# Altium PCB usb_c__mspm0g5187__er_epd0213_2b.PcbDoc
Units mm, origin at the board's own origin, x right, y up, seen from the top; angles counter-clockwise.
Board outline 82 x 52 mm, 2 copper layers (Top, Bottom), stack 0 mm thick; 41 components, 34 nets, 208 pads, 91 vias.
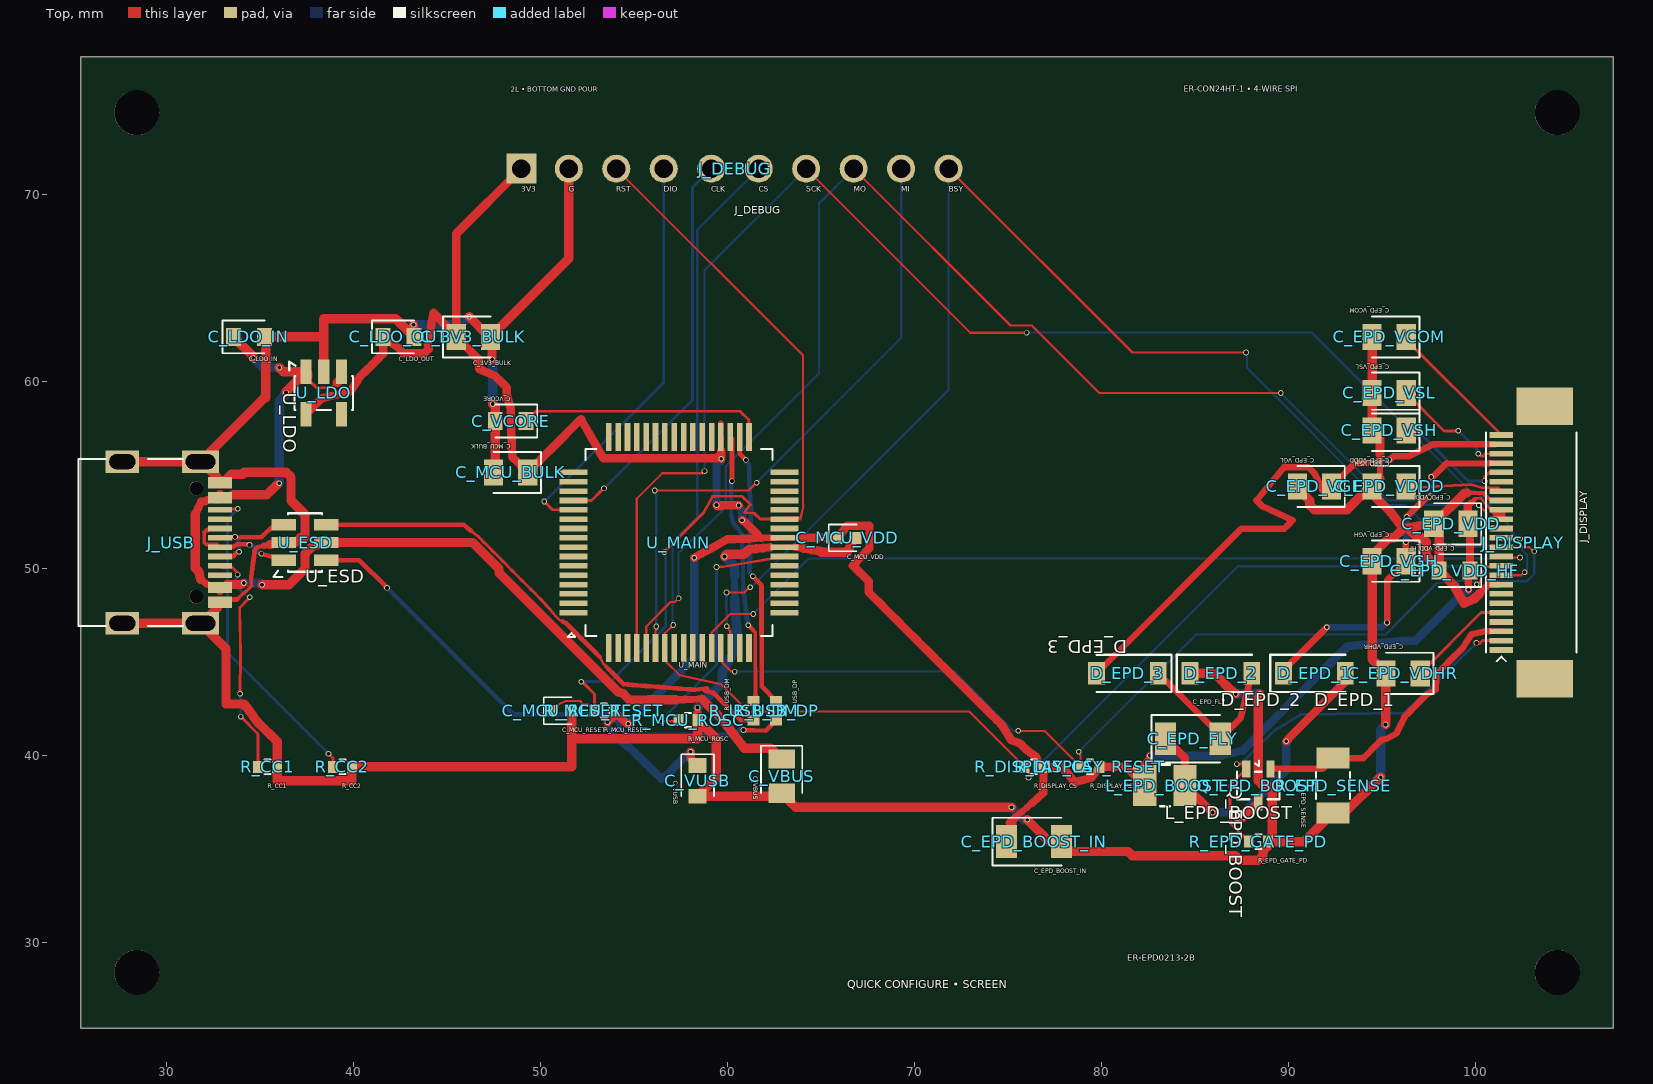
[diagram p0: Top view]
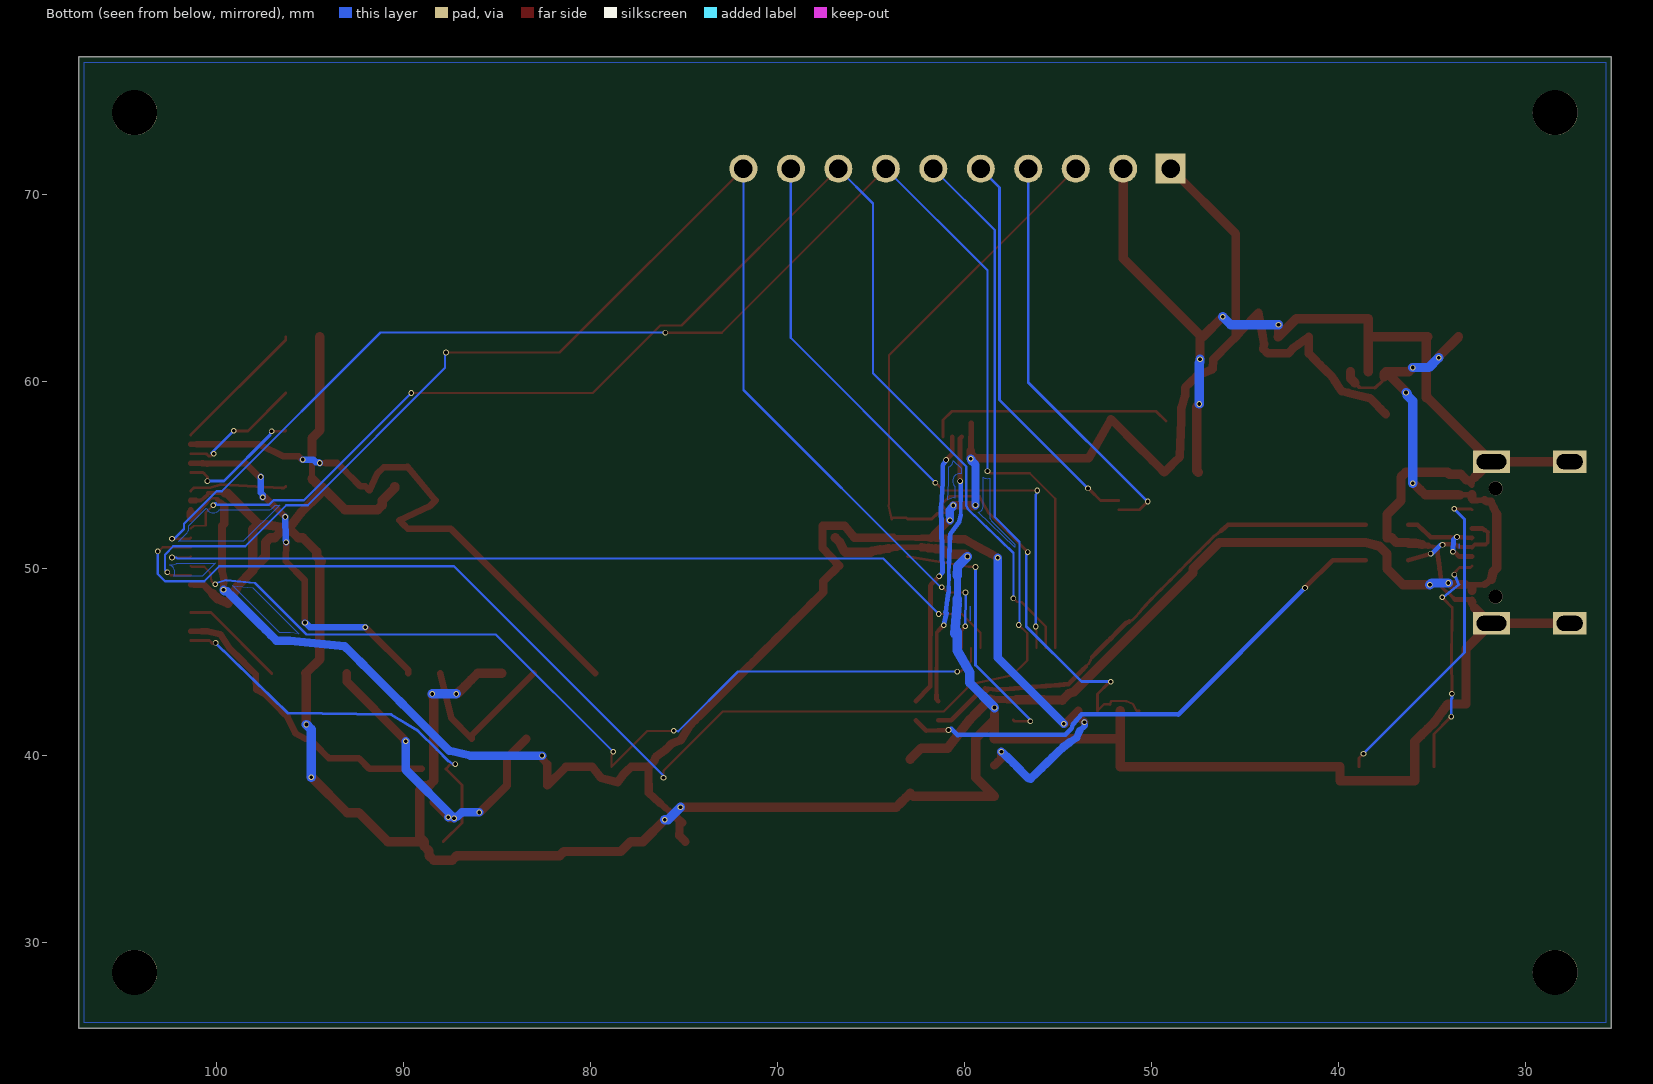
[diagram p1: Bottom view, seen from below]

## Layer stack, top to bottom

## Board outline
25.4,77.4 107.4,77.4 107.4,25.4 25.4,25.4

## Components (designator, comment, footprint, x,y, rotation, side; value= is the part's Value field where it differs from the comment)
C_3V3_BULK "" TSCIRCUIT-2.8500x1.4000mm 46.4,62.4 r0 top
C_EPD_BOOST_IN "" TSCIRCUIT-4.0500x1.7500mm 76.4,35.4 r0 top
C_EPD_FLY "" TSCIRCUIT-4.0500x1.7500mm 84.9,40.9 r0 top
C_EPD_VCOM "" TSCIRCUIT-2.8500x1.4000mm 95.4,62.4 r180 top
C_EPD_VDD "" TSCIRCUIT-2.8500x1.4000mm 98.7,52.4 r180 top
C_EPD_VDD_HF "" TSCIRCUIT-2.4500x0.9500mm 98.9,49.9 r180 top
C_EPD_VDDD "" TSCIRCUIT-2.8500x1.4000mm 95.4,54.4 r180 top
C_EPD_VDHR "" TSCIRCUIT-2.8500x1.4000mm 96.15,44.4 r180 top
C_EPD_VGH "" TSCIRCUIT-2.8500x1.4000mm 95.4,50.4 r180 top
C_EPD_VGL "" TSCIRCUIT-2.8500x1.4000mm 91.4,54.4 r180 top
C_EPD_VSH "" TSCIRCUIT-2.8500x1.4000mm 95.4,57.4 r180 top
C_EPD_VSL "" TSCIRCUIT-2.8500x1.4000mm 95.4,59.4 r180 top
C_LDO_IN "" TSCIRCUIT-2.4500x0.9500mm 34.4,62.4 r0 top
C_LDO_OUT "" TSCIRCUIT-2.4500x0.9500mm 42.4,62.4 r0 top
C_MCU_BULK "" TSCIRCUIT-2.8500x1.4000mm 48.4,55.15 r180 top
C_MCU_RESET "" TSCIRCUIT-1.5600x0.6400mm 51.15,42.4 r0 top
C_MCU_VDD "" TSCIRCUIT-1.5600x0.6400mm 66.4,51.65 r0 top
C_VBUS "" TSCIRCUIT-1.4000x2.8500mm 62.9,38.9 r270 top
C_VCORE "" TSCIRCUIT-2.4500x0.9500mm 48.4,57.9 r180 top
C_VUSB "" TSCIRCUIT-0.9500x2.4500mm 58.4,38.65 r270 top
D_EPD_1 "" TSCIRCUIT-4.2000x1.2000mm 91.4,44.4 r0 top
D_EPD_2 "" TSCIRCUIT-4.2000x1.2000mm 86.4,44.4 r0 top
D_EPD_3 "" TSCIRCUIT-4.2000x1.2000mm 81.4,44.4 r180 top
J_DEBUG "" TSCIRCUIT-24.3600x1.5000mm 60.4,71.4 r0 top
J_DISPLAY "" TSCIRCUIT-4.4500x16.5800mm 103,51.4 r90 top
J_USB "" TSCIRCUIT-6.7732x9.8502mm 30.113,51.4 r90 top
L_EPD_BOOST "" TSCIRCUIT-3.4000x2.2000mm 83.4,38.4 r0 top
Q_EPD_BOOST "" TSCIRCUIT-1.7500x2.7000mm 88.4,38.4 r270 top
R_CC1 "" TSCIRCUIT-1.5600x0.6400mm 35.4,39.4 r0 top
R_CC2 "" TSCIRCUIT-1.5600x0.6400mm 39.4,39.4 r0 top
R_DISPLAY_CS "" TSCIRCUIT-1.5600x0.6400mm 76.4,39.4 r0 top
R_DISPLAY_RESET "" TSCIRCUIT-1.5600x0.6400mm 79.4,39.4 r0 top
R_EPD_GATE_PD "" TSCIRCUIT-1.5600x0.6400mm 88.4,35.4 r0 top
R_EPD_SENSE "" TSCIRCUIT-1.7500x4.0500mm 92.4,38.4 r270 top
R_MCU_RESET "" TSCIRCUIT-1.5600x0.6400mm 53.4,42.4 r0 top
R_MCU_ROSC "" TSCIRCUIT-1.5600x0.6400mm 57.9,41.9 r0 top
R_USB_DM "" TSCIRCUIT-0.6400x1.5600mm 61.4,42.4 r90 top
R_USB_DP "" TSCIRCUIT-0.6400x1.5600mm 62.6,42.4 r90 top
U_ESD "" TSCIRCUIT-3.6000x2.5000mm 37.4,51.4 r0 top
U_LDO "" TSCIRCUIT-2.5000x3.6000mm 38.4,59.4 r270 top
U_MAIN "" TSCIRCUIT-12.8000x12.8000mm 57.4,51.4 r0 top

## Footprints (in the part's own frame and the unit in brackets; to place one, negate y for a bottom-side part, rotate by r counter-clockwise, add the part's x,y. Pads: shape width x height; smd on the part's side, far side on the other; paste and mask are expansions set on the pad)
TSCIRCUIT-0.6400x1.5600mm [mm]
  rect 0.54x0.64 smd: 1(-0.51,0) 2(0.51,0)
  silkscreen extent -0.15,-0.38 0.15,0.38
TSCIRCUIT-0.9500x2.4500mm [mm]
  rect 0.8x0.95 smd: 1(-0.825,0) 2(0.825,0)
  silkscreen extent -1.43,-0.87 0.82,0.87
TSCIRCUIT-1.4000x2.8500mm [mm]
  rect 1.025x1.4 smd: 1(-0.913,0) 2(0.913,0)
  silkscreen extent -1.62,-1.1 0.91,1.1
TSCIRCUIT-1.5600x0.6400mm [mm]
  rect 0.54x0.64 smd: 1(-0.51,0) 2(0.51,0)
  silkscreen extent -0.98,-0.72 0.51,0.72
TSCIRCUIT-1.7500x2.7000mm [mm]
  rect 0.925x0.45 smd: 1(-0.888,-0.65) 2(-0.888,0.65) 3(0.887,0)
  silkscreen extent -1.32,-1.14 0.73,1.13
TSCIRCUIT-1.7500x4.0500mm [mm]
  rect 1.125x1.75 smd: 1(-1.463,0) 2(1.462,0)
  silkscreen extent -0.73,-0.91 0.73,0.91
TSCIRCUIT-2.4500x0.9500mm [mm]
  rect 0.8x0.95 smd: 1(-0.825,0) 2(0.825,0)
  silkscreen extent -1.42,-0.87 0.82,0.87
TSCIRCUIT-2.5000x3.6000mm [mm]
  rect 1.325x0.6 smd: 1(-1.137,-0.95) 2(-1.137,0) 3(-1.137,0.95) 4(1.138,0.95) 5(1.138,-0.95)
  silkscreen extent -1.69,-1.84 0.91,1.56
TSCIRCUIT-2.8500x1.4000mm [mm]
  rect 1.025x1.4 smd: 1(-0.913,0) 2(0.913,0)
  silkscreen extent -1.63,-1.1 0.91,1.1
TSCIRCUIT-3.4000x2.2000mm [mm]
  rect 1.25x2.2 smd: 1(-1.075,0) 2(1.075,0)
  silkscreen extent -0.26,-1.11 0.26,1.11
TSCIRCUIT-3.6000x2.5000mm [mm]
  rect 1.325x0.6 smd: 1(-1.137,-0.95) 2(-1.137,0) 3(-1.137,0.95) 4(1.138,0.95) 5(1.138,0) 6(1.138,-0.95)
  silkscreen extent -1.69,-1.84 0.91,1.56
TSCIRCUIT-4.0500x1.7500mm [mm]
  rect 1.125x1.75 smd: 1(-1.462,0) 2(1.463,0)
  silkscreen extent -2.22,-1.28 1.46,1.27
TSCIRCUIT-4.2000x1.2000mm [mm]
  rect 0.9x1.2 smd: 1(-1.65,0) 2(1.65,0)
  silkscreen extent -2.36,-1 1.65,1
TSCIRCUIT-4.4500x16.5800mm [mm]
  rect 0.3x1.25 smd: 1(-5.75,1.6) 2(-5.25,1.6) 3(-4.75,1.6) 4(-4.25,1.6) 5(-3.75,1.6) 6(-3.25,1.6) 7(-2.75,1.6) 8(-2.25,1.6) 9(-1.75,1.6) 10(-1.25,1.6) 11(-0.75,1.6) 12(-0.25,1.6) 13(0.25,1.6) 14(0.75,1.6) 15(1.25,1.6) 16(1.75,1.6) 17(2.25,1.6) 18(2.75,1.6) 19(3.25,1.6) 20(3.75,1.6) 21(4.25,1.6) 22(4.75,1.6) 23(5.25,1.6) 24(5.75,1.6)
  rect 2x3 smd: 25(7.29,-0.725) 26(-7.29,-0.725)
  silkscreen extent -6.35,-2.43 5.9,2.42
TSCIRCUIT-6.7732x9.8502mm [mm]
  rect 0.3x1.3 smd: 1(-3.35,-2.737) 2(-3.05,-2.737) 3(-2.55,-2.737) 4(-2.25,-2.737) 5(-1.75,-2.737) 6(-1.25,-2.737) 7(-0.75,-2.737) 8(-0.25,-2.737) 9(0.25,-2.737) 10(0.75,-2.737) 11(1.25,-2.737) 12(1.75,-2.737) 13(2.55,-2.737) 14(2.25,-2.737) 15(3.35,-2.737) 16(3.05,-2.737)
  rect 1.2x2 hole 0.8 slot 1.6 at 90 deg: 17(-4.325,-1.693) 18(4.325,-1.693)
  rect 1.2x1.8 hole 0.8 slot 1.4 at 90 deg: 19(4.325,2.487) 20(-4.325,2.487)
  round 0.75 hole 0.75 unplated: NPTH-1(-2.9,-1.468) NPTH-2(2.9,-1.468)
  silkscreen extent -4.47,-0.75 4.47,4.83
TSCIRCUIT-12.8000x12.8000mm [mm]
  rect 1.5x0.3 smd: 1(-5.65,-3.75) 2(-5.65,-3.25) 3(-5.65,-2.75) 4(-5.65,-2.25) 5(-5.65,-1.75) 6(-5.65,-1.25) 7(-5.65,-0.75) 8(-5.65,-0.25) 9(-5.65,0.25) 10(-5.65,0.75) 11(-5.65,1.25) 12(-5.65,1.75) 13(-5.65,2.25) 14(-5.65,2.75) 15(-5.65,3.25) 16(-5.65,3.75) 33(5.65,3.75) 34(5.65,3.25) 35(5.65,2.75) 36(5.65,2.25) 37(5.65,1.75) 38(5.65,1.25) 39(5.65,0.75) 40(5.65,0.25) 41(5.65,-0.25) 42(5.65,-0.75) 43(5.65,-1.25) 44(5.65,-1.75) 45(5.65,-2.25) 46(5.65,-2.75) 47(5.65,-3.25) 48(5.65,-3.75)
  rect 0.3x1.5 smd: 17(-3.75,5.65) 18(-3.25,5.65) 19(-2.75,5.65) 20(-2.25,5.65) 21(-1.75,5.65) 22(-1.25,5.65) 23(-0.75,5.65) 24(-0.25,5.65) 25(0.25,5.65) 26(0.75,5.65) 27(1.25,5.65) 28(1.75,5.65) 29(2.25,5.65) 30(2.75,5.65) 31(3.25,5.65) 32(3.75,5.65) 49(3.75,-5.65) 50(3.25,-5.65) 51(2.75,-5.65) 52(2.25,-5.65) 53(1.75,-5.65) 54(1.25,-5.65) 55(0.75,-5.65) 56(0.25,-5.65) 57(-0.25,-5.65) 58(-0.75,-5.65) 59(-1.25,-5.65) 60(-1.75,-5.65) 61(-2.25,-5.65) 62(-2.75,-5.65) 63(-3.25,-5.65) 64(-3.75,-5.65)
  silkscreen extent -5.95,-5.05 5,5
TSCIRCUIT-24.3600x1.5000mm [mm]
  rect 1.6x1.6 hole 1: 1(-11.43,0)
  round 1.5 hole 1: 2(-8.89,0) 3(-6.35,0) 4(-3.81,0) 5(-1.27,0) 6(1.27,0) 7(3.81,0) 8(6.35,0) 9(8.89,0) 10(11.43,0)

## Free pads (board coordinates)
  round 2.4 hole 2.4 unplated: NPTH-3(28.4,28.4) NPTH-4(104.4,28.4) NPTH-5(28.4,74.4) NPTH-6(104.4,74.4)

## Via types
v1: diameter 0.3, hole 0.2, Top to Bottom, 91 vias

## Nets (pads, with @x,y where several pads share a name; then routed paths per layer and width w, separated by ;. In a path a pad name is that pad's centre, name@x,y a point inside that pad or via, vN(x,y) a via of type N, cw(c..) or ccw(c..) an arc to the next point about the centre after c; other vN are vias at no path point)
".J_DEBUG > .pin4 to .U_MAIN > .pin12": J_DEBUG.4 U_MAIN.12 | length 22.2
  Top w0.15: v1(50.2,53.593) 50.643,53.15 U_MAIN.12
  Bottom w0.15: v1(50.2,53.593) 50.215,53.593 56.59,59.968 J_DEBUG.4
".J_DEBUG > .pin5 to .U_MAIN > .pin13": J_DEBUG.5 U_MAIN.13 | length 21.4
  Top w0.15: U_MAIN.13 52.732,53.65 53.275,54.193 53.293,54.193 v1(53.395,54.295)
  Bottom w0.15: v1(53.395,54.295) 58.128,59.028 58.128,70.316 58.128,70.398 J_DEBUG.5
".J_DISPLAY > .pin5 to .C_EPD_VDHR > .pin1": C_EPD_VDHR.1 J_DISPLAY.5 | length 5.7
  Top w0.15: C_EPD_VDHR.1 100.313,47.65 J_DISPLAY.5
".J_DISPLAY > .pin18 to .C_EPD_VDDD > .pin1": C_EPD_VDDD.1 J_DISPLAY.18 | length 5.2
  Top w0.15: C_EPD_VDDD.1 96.403,54.31 96.526,54.31 99.77,54.5 100.358,54.332 101.24,54.31 J_DISPLAY.18
".J_DISPLAY > .pin20 to .C_EPD_VSH > .pin1": C_EPD_VSH.1 J_DISPLAY.20 | length 6.6
  Top w0.15: C_EPD_VSH.1 96.362,57.351 v1(97.07,57.351) ; v1(100.503,54.686) 100.503,54.911 100.677,55.085 100.742,55.15 J_DISPLAY.20
  Bottom w0.15: v1(97.07,57.351) 97.144,57.277 97.144,57.166 99.624,54.686 v1(100.503,54.686)
".J_DISPLAY > .pin22 to .C_EPD_VSL > .pin1": C_EPD_VSL.1 J_DISPLAY.22 | length 6.8
  Top w0.15: C_EPD_VSL.1 98.341,57.372 v1(99.099,57.372) ; v1(100.159,56.142) 100.305,56.031 100.449,56.031 100.568,56.15 J_DISPLAY.22
  Bottom w0.15: v1(99.099,57.372) 99.157,57.314 100.289,56.182 v1(100.159,56.142)
".J_DISPLAY > .pin24 to .C_EPD_VCOM > .pin1": C_EPD_VCOM.1 J_DISPLAY.24 | length 7.4
  Top w0.15: C_EPD_VCOM.1 96.312,62.238 J_DISPLAY.24
".U_MAIN > .pin42 to .R_MCU_ROSC > .pin1": R_MCU_ROSC.1 U_MAIN.42 | length 14.1
  Top w0.15: v1(56.473,41.835) 57.325,41.835 R_MCU_ROSC.1 ; v1(59.411,50.089) 59.429,50.107 59.777,50.106 U_MAIN.42
  Bottom w0.15: v1(56.473,41.835) 56.447,41.861 56.447,41.875 59.411,44.838 v1(59.411,50.089)
DISPLAY_BUSY_N: J_DEBUG.10 J_DISPLAY.9 U_MAIN.51 | length 73.5
  Top w0.12: v1(59.945,48.725) 60.896,48.725 61.106,48.935 61.158,48.935 v1(61.223,49) ; v1(59.964,46.92) 60.093,46.817 60.093,46.726 60.15,46.67 U_MAIN.51 ; J_DEBUG.10 81.666,61.564 v1(87.742,61.564) ; J_DISPLAY.9 102.472,49.65 102.598,49.776 102.612,49.776 v1(102.645,49.809)
  Bottom w0.12: v1(59.945,48.725) 59.936,48.716 59.936,48.646 v1(59.964,46.92) ; v1(61.223,49) 61.267,49 71.83,59.563 J_DEBUG.10 ; v1(87.742,61.564) 87.788,61.518 87.788,61.482 87.788,60.745 95.141,53.392 96.285,53.392 98.48,51.197 102.335,51.197 102.78,50.752 102.78,49.944 v1(102.645,49.809)
DISPLAY_CS_N: J_DEBUG.6 J_DISPLAY.12 R_DISPLAY_CS.1 U_MAIN.58 | length 85.9
  Top w0.12: v1(57.094,46.987) 56.65,46.543 U_MAIN.58 56.65,45.093 57.449,44.294 59.655,43.814 61.112,42.358 72.932,42.358 R_DISPLAY_CS.1 76.106,39.184 v1(76.106,38.818) ; J_DISPLAY.12 102.897,51.15 103.076,50.971 103.117,50.971 v1(103.166,50.922)
  Bottom w0.12: v1(57.094,46.987) 57.056,47.025 57.056,47.046 57.056,51.428 58.388,52.759 58.388,68.118 J_DEBUG.6 ; v1(76.106,38.818) 76.055,38.869 87.316,50.131 99.877,50.131 100.675,49.333 102.779,49.333 103.166,49.72 v1(103.166,50.922)
DISPLAY_DC: J_DISPLAY.11 U_MAIN.53 | length 46.8
  Top w0.12: U_MAIN.53 59.15,46.572 60.16,47.582 61.321,47.582 61.347,47.608 v1(61.381,47.574) ; J_DISPLAY.11 101.45,50.6 v1(102.4,50.6)
  Bottom w0.12: v1(61.381,47.574) 64.353,50.546 95.398,50.546 102.123,50.546 102.177,50.6 v1(102.4,50.6)
DISPLAY_MISO: J_DEBUG.9 U_MAIN.59 | length 34.1
  Top w0.12: v1(56.115,54.184) 61.124,54.184 61.468,54.528 v1(61.557,54.599) ; U_MAIN.59 56.15,46.685 56.196,46.731 56.196,46.895 v1(56.186,46.905)
  Bottom w0.12: v1(56.115,54.184) 56.058,54.127 56.058,54.101 56.186,53.973 v1(56.186,46.905) ; v1(61.557,54.599) 69.29,62.35 J_DEBUG.9
DISPLAY_MOSI: J_DEBUG.8 J_DISPLAY.14 U_MAIN.60 | length 73.5
  Top w0.12: U_MAIN.60 55.65,46.912 56.95,48.212 57.186,48.212 v1(57.383,48.409) ; J_DEBUG.8 75.137,63.013 76.276,63.013 79.888,59.4 89.529,59.4 v1(89.6,59.4) ; v1(100.191,53.388) 100.591,53.008 100.591,52.312 101.228,52.289 J_DISPLAY.14
  Bottom w0.12: v1(57.383,48.409) 57.383,50.842 59.826,53.195 59.904,53.363 59.904,55.468 60.536,56.099 64.891,60.454 64.891,69.541 J_DEBUG.8 ; v1(89.6,59.4) 95.341,53.659 96.97,53.659 97.211,53.419 99.868,53.419 99.98,53.419 100.076,53.515 100.084,53.515 v1(100.191,53.388)
DISPLAY_RESET_N: J_DISPLAY.10 R_DISPLAY_RESET.1 U_MAIN.52 | length 50.1
  Top w0.12: U_MAIN.52 59.65,45.051 59.863,44.838 60.207,44.494 v1(60.392,44.494) ; v1(75.556,41.328) 76.991,41.299 R_DISPLAY_RESET.1 78.89,40.022 78.799,40.112 v1(78.799,40.203) ; v1(100.086,49.16) 100.285,49.33 100.347,49.778 100.673,50.103 101.353,50.103 J_DISPLAY.10
  Bottom w0.12: v1(60.392,44.494) 72.12,44.494 75.315,41.299 v1(75.556,41.328) ; v1(78.799,40.203) 85.074,46.478 95.197,46.478 97.957,49.238 99.513,49.386 100.03,49.238 v1(100.086,49.16)
DISPLAY_SCLK: J_DEBUG.7 J_DISPLAY.13 U_MAIN.61 | length 78.2
  Top w0.12: U_MAIN.61 55.15,53.743 56.507,55.1 58.65,55.1 58.726,55.176 v1(58.77,55.22) ; J_DEBUG.7 72.984,62.626 75.825,62.626 75.996,62.626 v1(76,62.63) ; J_DISPLAY.13 101.45,51.6 v1(102.4,51.6)
  Bottom w0.12: v1(58.77,55.22) 58.77,65.96 J_DEBUG.7 ; v1(76,62.63) 91.241,62.63 99.732,54.139 100.023,54.139 101.761,52.402 101.761,52.117 102.265,51.612 102.388,51.612 v1(102.4,51.6)
EPD_GDR: J_DISPLAY.2 Q_EPD_BOOST.1 R_EPD_GATE_PD.1 | length 22
  Top w0.15: v1(87.248,39.546) 87.491,39.546 Q_EPD_BOOST.1 86.892,38.43 86.892,36.398 R_EPD_GATE_PD.1 ; v1(100.067,46.029) 100.114,45.982 100.22,45.982 100.388,46.15 J_DISPLAY.2
  Bottom w0.15: v1(87.248,39.546) 87.252,39.55 87.381,39.55 87.617,39.717 88.226,40.318 89.234,41.325 90.667,42.196 96.208,42.284 v1(100.067,46.029)
EPD_PUMP: C_EPD_FLY.2 D_EPD_2.2 D_EPD_3.1 | length 8.9
  Top w0.35: D_EPD_3.1 86.362,41.087 C_EPD_FLY.2 87.468,42.025 D_EPD_2.2
EPD_RESE: J_DISPLAY.3 Q_EPD_BOOST.2 R_EPD_SENSE.1 | length 16
  Top w0.3: J_DISPLAY.3@100.812,46.65 101.106,46.65 J_DISPLAY.3
  Top w0.35: Q_EPD_BOOST.2 91.826,39.288 R_EPD_SENSE.1 92.721,39.862 93.042,39.861 93.364,39.861 93.685,39.86 94.006,39.86 94.251,40.105 94.496,40.35 94.741,40.595 94.985,40.84 95.275,40.9 95.801,41.191 96.21,42.064 96.454,42.309 96.699,42.554 96.944,42.799 97.189,43.044 97.434,43.289 97.9,43.525 97.923,44.063 97.922,44.348 98.159,44.585 98.396,44.822 98.633,45.059 98.87,45.296 99.107,45.533 99.344,45.77 99.825,46.5 100.518,46.65 J_DISPLAY.3@100.812,46.65
EPD_SWITCH: C_EPD_FLY.1 D_EPD_1.2 L_EPD_BOOST.2 Q_EPD_BOOST.3 | length 19.6
  Top w0.45: C_EPD_FLY.1 84.475,39.863 L_EPD_BOOST.2 84.48,38.4 85.879,37.001 85.924,37.001 v1(85.963,36.962) ; v1(87.308,36.655) v1@87.543,36.655 ; v1(87.625,36.7) v1@87.543,36.655 ; v1(89.894,40.764) 90.006,40.876 90.006,40.911 93.05,43.954 D_EPD_1.2 ; v1@87.543,36.655 Q_EPD_BOOST.3 v1@87.543,36.655
  Bottom w0.45: v1(85.963,36.962) 86.9,36.962 87.12,36.741 87.222,36.741 v1(87.625,36.7) ; v1(87.308,36.655) 87.344,36.691 89.894,39.241 v1(89.894,40.764)
EPD_VGH: C_EPD_VGH.1 D_EPD_1.1 J_DISPLAY.21 | length 19.7
  Top w0.3: 100.775,55.65 100.837,55.65 100.931,55.65 101.025,55.65 101.119,55.65 101.213,55.65 101.306,55.65 J_DISPLAY.21
  Top w0.35: D_EPD_1.1 89.75,44.56 91.935,46.745 91.938,46.745 v1(92.064,46.871) ; v1(95.285,47.116) 95.285,49.372 C_EPD_VGH.1 96.321,50.408 v1(96.294,51.409) ; v1(96.341,52.77) 96.431,52.859 96.435,52.859 97.391,53.815 v1(97.537,53.815) ; v1(97.649,54.908) 97.663,54.894 97.713,54.894 98.469,55.643 100.51,55.607 100.744,55.65 100.775,55.65
  Bottom w0.35: v1(92.064,46.871) 95.015,46.871 95.226,47.081 95.25,47.081 v1(95.285,47.116) ; v1(96.294,51.409) 96.278,51.479 96.278,51.494 96.302,51.519 v1(96.341,52.77) ; v1(97.537,53.815) 97.538,53.816 97.538,53.955 97.649,54.066 v1(97.649,54.908)
EPD_VGL: C_EPD_VGL.1 D_EPD_3.2 J_DISPLAY.23 | length 31.7
  Top w0.3: J_DISPLAY.23@101.066,56.65 J_DISPLAY.23
  Top w0.325: 94.182,55.654 v1(94.489,55.654)
  Top w0.35: D_EPD_3.2 79.991,44.641 80.233,44.883 80.474,45.124 80.716,45.366 80.957,45.607 81.199,45.849 81.44,46.09 81.681,46.331 81.923,46.573 82.164,46.814 82.406,47.056 82.647,47.297 82.888,47.538 83.13,47.78 83.371,48.021 83.613,48.263 83.854,48.504 84.096,48.746 84.337,48.987 84.578,49.228 84.82,49.47 85.061,49.711 85.303,49.953 85.544,50.194 85.786,50.436 86.027,50.677 86.268,50.918 86.51,51.16 86.751,51.401 86.993,51.643 87.234,51.884 87.476,52.126 87.806,52.127 88.137,52.128 88.468,52.129 88.799,52.13 89.13,52.131 89.461,52.132 89.792,52.133 90.019,52.362 90.245,52.59 88.6,53.35 88.3,53.65 89.8,55.45 89.85,55.425 91.075,55.425 91.425,55.075 91.833,54.186 92.06,54.414 C_EPD_VGL.1 92.522,54.609 92.731,54.818 92.94,55.027 93.149,55.236 93.358,55.445 93.567,55.654 93.874,55.654 94.182,55.654 ; v1(95.404,55.836) 95.43,55.862 95.477,55.862 95.621,56.005 95.886,56.005 96.152,56.005 96.417,56.005 97.729,56.65 98.063,56.65 98.396,56.65 98.73,56.65 99.064,56.65 99.398,56.65 99.731,56.65 100.065,56.65 100.399,56.65 100.733,56.65 J_DISPLAY.23@101.066,56.65
  Bottom w0.35: v1(94.489,55.654) 94.57,55.704 94.71,55.704 94.842,55.836 95.123,55.836 v1(95.404,55.836)
GND: C_3V3_BULK.2 C_EPD_BOOST_IN.2 C_EPD_VCOM.2 C_EPD_VDD.2 C_EPD_VDD_HF.2 C_EPD_VDDD.2 C_EPD_VDHR.2 C_EPD_VGH.2 C_EPD_VGL.2 C_EPD_VSH.2 C_EPD_VSL.2 C_LDO_IN.2 C_LDO_OUT.2 C_MCU_BULK.2 C_MCU_RESET.2 C_MCU_VDD.2 C_VBUS.2 C_VCORE.2 C_VUSB.2 D_EPD_2.1 J_DEBUG.2 J_DISPLAY.8 J_DISPLAY.17 J_USB.1 J_USB.2 J_USB.15 J_USB.16 J_USB.17 J_USB.18 J_USB.19 J_USB.20 R_CC1.2 R_CC2.2 R_EPD_GATE_PD.2 R_EPD_SENSE.2 R_MCU_ROSC.2 U_ESD.2 U_LDO.2 U_MAIN.41 | length 234.2
  Top w0.188: 33.757,48.35 34.014,48.607 34.25,48.8 34.55,49.1
  Top w0.2: 34.527,49.525 34.527,49.12 34.55,49.1 ; 100.017,54.052 100.467,54.052 100.5,53.95 100.868,53.65 J_DISPLAY.17@101.134,53.65
  Top w0.225: 99.567,54.052 100.017,54.052
  Top w0.25: 34.527,49.525 34.585,50 34.642,50.475 34.7,50.95 34.837,51.15 35.18,51.221
  Top w0.275: J_USB.1@32.849,48.2 J_USB.2 33.303,48.35 33.757,48.35 ; J_USB.16 J_USB.15@33.153,54.754
  Top w0.288: J_USB.16 J_USB.15@32.849,54.6
  Top w0.3: J_USB.1@32.699,47.9 J_USB.1 J_USB.2@32.849,48.2 ; 32.699,54.9 J_USB.15 J_USB.16@32.849,54.6 ; 62.3,51.15 62.394,51.15 62.488,51.15 62.581,51.15 62.675,51.15 62.769,51.15 62.863,51.15 62.956,51.15 U_MAIN.41 63.144,51.15 63.238,51.15 63.331,51.15 63.425,51.15 63.519,51.15 U_MAIN.41@63.612,51.15 ; J_DISPLAY.17@101.134,53.65 J_DISPLAY.17 ; J_DISPLAY.8@101.213,49.15 101.306,49.15 J_DISPLAY.8
  Top w0.312: 58.397,42.241 v1(58.397,42.568) ; 94.908,56.111 94.909,55.676 94.911,55.241 C_EPD_VDDD.2@94.912,54.806
  Top w0.35: 35.18,51.221 35.523,51.291
  Top w0.375: 100.212,48.65 100.462,48.9 100.713,49.15 J_DISPLAY.8@101.213,49.15
  Top w0.4: U_MAIN.41@63.612,51.15 64.057,51.082
  Top w0.45: 61.917,51.108 62.3,51.15
  Top w0.475: 61.533,51.067 61.917,51.108 ; 64.057,51.082 64.502,51.015
  Top w0.5: J_USB.20 J_USB.17 ; J_USB.19 J_USB.18 ; J_USB.1@32.699,47.9 32.474,47.675 31.874,47.075 J_USB.17 ; 32.699,54.9 32.474,55.125 31.874,55.725 J_USB.18 ; J_USB.15@33.153,54.754 33.457,55.058 33.909,55.058 34.058,55.058 34.15,55.15 36.4,55.15 36.65,54.9 36.65,53.65 37.4,52.9 37.4,51.65 37.15,51.65 36.9,51.4 U_ESD.2 36.224,51.362 35.866,51.362 35.523,51.291 ; v1(43.2,63.05) 43.2,62.425 C_LDO_OUT.2 42.261,63.364 38.4,63.364 U_LDO.2 38.4,62.4 C_LDO_IN.2 35.299,62.326 35.299,59.145 35.225,59.145 J_USB.18 ; v1(46.186,63.476) 47.262,62.4 C_3V3_BULK.2 ; v1(47.4,61.2) 47.4,62.312 C_3V3_BULK.2 ; v1(47.438,58.808) 47.575,58.671 C_VCORE.2 47.575,55.237 C_MCU_BULK.2 ; J_DEBUG.2 51.51,66.597 C_3V3_BULK.2 ; 58.397,42.241 58.397,41.913 R_MCU_ROSC.2 ; v1(59.838,50.649) 59.953,50.765 59.954,50.765 60.89,50.765 61.15,51.025 61.533,51.067 ; 64.502,51.015 64.947,50.948 65.015,50.88 66.368,50.88 66.467,50.979 66.678,51.418 C_MCU_VDD.2 ; v1(75.192,37.241) 74.711,37.241 74.23,37.241 73.749,37.241 73.268,37.241 72.787,37.241 72.306,37.241 71.825,37.241 71.343,37.241 70.862,37.241 70.381,37.241 69.9,37.241 69.419,37.241 68.938,37.241 68.457,37.241 67.976,37.241 67.495,37.241 67.014,37.241 66.533,37.241 66.052,37.241 65.571,37.241 65.09,37.241 64.609,37.241 64.128,37.241 63.646,37.241 63.398,37.49 63.149,37.739 C_VBUS.2 62.737,37.825 C_VUSB.2 59.4,38.825 59.4,40.91 R_MCU_ROSC.2 ; v1(76.034,36.566) 77.2,35.4 C_EPD_BOOST_IN.2 78.128,35.135 78.393,34.87 78.892,34.87 79.391,34.87 79.891,34.87 80.39,34.87 80.889,34.87 81.389,34.87 81.43,34.87 81.65,34.65 87.15,34.65 87.4,34.4 88.4,34.4 88.65,34.65 88.65,34.9 88.9,35.15 88.9,35.4 R_EPD_GATE_PD.2 ; D_EPD_2.1 85.181,44.4 85.611,44.4 86.042,44.4 86.386,44.056 86.729,43.713 87.073,43.369 87.122,43.369 v1(87.19,43.301) ; v1(88.472,43.299) 88.472,43.222 88.4,43.15 88.4,38.65 88.65,38.4 88.9,38.4 89.15,38.15 89.15,35.64 R_EPD_GATE_PD.2 ; C_EPD_VGL.2 90.487,54.312 91.15,53.65 91.15,53.4 91.4,53.15 93.15,53.15 94.4,54.4 C_EPD_VDDD.2 ; C_EPD_VSL.2 C_EPD_VSH.2 94.906,56.981 94.906,56.546 94.908,56.111 ; C_EPD_VSL.2 C_EPD_VCOM.2 ; C_EPD_VDDD.2@94.912,54.806 94.7,54.603 C_EPD_VDDD.2 ; v1(94.946,38.841) 94.904,38.799 94.879,38.799 93.017,36.938 R_EPD_SENSE.2 90.863,35.4 R_EPD_GATE_PD.2 ; v1(95.209,41.664) 95.209,44.371 C_EPD_VDHR.2 94.487,45.15 C_EPD_VGH.2 94.4,50.4 94.65,50.65 94.65,50.9 95.4,51.65 95.65,51.65 96.15,52.15 ; 99.567,54.052 99.439,54.052 C_EPD_VDD.2 ; 100.212,48.65 99.963,48.4 99.4,48.15 98.913,49.025 98.913,49.062 C_EPD_VDD_HF.2 ; J_USB.17 33.168,45.713 33.168,42.759 34.134,42.759 34.381,42.432 34.628,42.105 34.875,41.777 35.22,41.436 35.565,41.094 35.909,40.753 35.91,40.302 35.91,39.851 R_CC1.2 35.91,38.65 39.91,38.65 R_CC2.2 40.391,39.4 40.872,39.4 41.353,39.4 41.835,39.4 42.316,39.4 42.797,39.4 43.278,39.4 43.759,39.4 44.24,39.4 44.721,39.4 45.202,39.4 45.684,39.4 51.66,39.4 C_MCU_RESET.2 51.66,40.9 54.15,40.9 58.41,40.9 R_MCU_ROSC.2 ; C_EPD_VDDD.2 94.487,54.016 95.488,53.016 96.15,52.15 ; 96.15,52.15 96.4,52.15 96.9,51.65 97.15,51.65 97.4,51.4 97.4,50.65 98.075,49.975 C_EPD_VDD_HF.2 ; 96.15,52.15 97.347,52.347 97.735,52.347 C_EPD_VDD.2 ; C_EPD_VDD.2 98.075,52.112 C_EPD_VDD_HF.2
  Bottom w0.375: 60.38,49.618 60.38,49.118 60.387,48.754 60.393,48.389
  Bottom w0.5: v1(43.2,63.05) 45.76,63.05 v1(46.186,63.476) ; v1(47.4,61.2) 47.405,61.195 47.405,61.043 47.438,61.011 v1(47.438,58.808) ; v1(58.397,42.568) 59.723,43.894 59.723,44.462 60.385,45.619 60.385,46.119 60.384,46.619 60.525,46.525 60.382,48.118 60.4,48.025 60.393,48.389 ; v1(59.838,50.649) 60.108,50.384 60.379,50.118 60.38,49.618 ; v1(75.192,37.241) 75.867,36.566 v1(76.034,36.566) ; v1(87.19,43.301) 88.47,43.301 v1(88.472,43.299) ; v1(94.946,38.841) 94.946,41.401 v1(95.209,41.664)
MAIN_RESET: C_MCU_RESET.1 J_DEBUG.3 R_MCU_RESET.1 U_MAIN.38 | length 47.3
  Top w0.12: C_MCU_RESET.1 50.798,42.4 50.991,42.753 51.351,42.911 51.751,42.92 52.151,42.911 52.215,42.72 52.21,42.749 52.541,42.749 R_MCU_RESET.1 ; J_DEBUG.3 64.038,61.412 64.038,53.428 64.071,53.382 63.891,52.627 63.819,52.723 63.123,52.723 U_MAIN.38
  Top w0.15: v1(52.183,43.957) 52.241,43.899 52.285,43.899 52.89,43.295 R_MCU_RESET.1 ; v1(56.616,50.886) 58.698,52.968 59.2,53.875 60.775,53.875 61.225,53.425 60.913,53.009 61.435,52.968 61.753,52.65 U_MAIN.38
  Bottom w0.15: v1(52.183,43.957) 53.739,43.957 56.697,46.915 56.697,50.736 56.582,50.852 v1(56.616,50.886)
MSP_VCORE: C_VCORE.1 U_MAIN.32 | length 13.2
  Top w0.15: C_VCORE.1 49.75,58.425 60.678,58.425 61.15,57.952 U_MAIN.32
usb-dm-mcu: R_USB_DM.2 U_MAIN.30 | length 14.6
  Top w0.188: 61.367,46.713 61.494,46.579 61.494,46.342 61.495,46.105 61.495,45.868 61.495,45.631 61.496,45.394 61.496,45.157 61.496,44.92 61.497,44.682
  Top w0.212: 61.497,44.445 61.497,44.682
  Top w0.219: 61.497,44.445 61.497,44.208 61.498,43.971 61.498,43.734 61.498,43.497 61.499,43.26
  Top w0.238: v1(61.112,46.98) 61.239,46.846 61.367,46.713
  Top w0.25: U_MAIN.30 60.237,56.963 60.237,56.735 60.237,56.508 60.237,56.28 60.237,56.052 60.237,55.825 60.237,55.597 60.237,55.369 60.237,55.141 60.237,54.914 v1(60.237,54.686) ; R_USB_DM.2 61.499,43.023 61.499,43.26
  Bottom w0.188: 60.209,52.869 60.209,53.116 60.209,53.362 60.209,53.609
  Bottom w0.2: 60.833,50.309 60.835,50.093 60.837,49.877 60.839,49.662
  Bottom w0.212: 60.839,49.662 60.842,49.446 60.844,49.23 60.846,49.014
  Bottom w0.225: 60.846,49.014 60.848,48.798
  Bottom w0.25: 60.209,52.869 60.275,52.525 60.763,51.858 60.773,51.637 60.783,51.415 60.793,51.194 60.803,50.973 60.813,50.752 60.823,50.53 60.833,50.309 ; 60.209,53.609 60.209,53.855 60.209,54.102 60.209,54.348 60.209,54.595 60.209,54.658 v1(60.237,54.686) ; 60.848,48.798 60.881,48.571 60.914,48.344 60.947,48.116 60.98,47.889 61.013,47.662 60.962,47.65 v1(61.112,46.98)
usb-dm-phy: R_USB_DM.1 U_ESD.4 | length 27.4
  Top w0.12: 50.649,47.653 50.805,47.471 50.908,47.365
  Top w0.125: 50.908,47.365 51.01,47.26 ; 53.26,45.1 53.35,44.92 53.505,44.763
  Top w0.138: 50.492,47.834 50.649,47.653 ; 53.17,45.28 53.26,45.1
  Top w0.15: 50.336,48.016 50.492,47.834 ; 51.01,47.26 51.19,47.17
  Top w0.156: 48.15,50.231 48.319,50.062 48.488,49.892 48.657,49.723 48.826,49.553 48.995,49.384 49.164,49.215 49.333,49.045 49.502,48.876 49.672,48.707 49.841,48.537 50.01,48.368
  Top w0.162: 46.439,51.893 46.569,51.796 46.7,51.7 46.798,51.588 46.967,51.418 47.136,51.249 47.305,51.079 47.474,50.91 47.643,50.74 47.812,50.571 47.981,50.401 48.15,50.231 ; 50.01,48.368 50.173,48.192 50.336,48.016
  Top w0.175: 46.259,52.045 46.439,51.893
  Top w0.2: 53.505,44.763 53.661,44.605
  Top w0.225: 53.006,45.444 53.17,45.28
  Top w0.25: U_ESD.4 38.783,52.35 39.028,52.35 39.274,52.35 39.519,52.35 39.765,52.35 40.01,52.35 40.255,52.35 40.501,52.35 40.746,52.35 40.992,52.35 41.237,52.35 41.483,52.35 41.728,52.35 41.973,52.35 42.219,52.35 42.464,52.35 42.71,52.35 42.955,52.35 43.201,52.35 43.446,52.35 43.691,52.35 43.937,52.35 44.182,52.35 44.428,52.35 44.673,52.35 44.919,52.35 45.164,52.35 45.409,52.35 45.655,52.35 45.9,52.35 46.08,52.198 46.259,52.045 ; 51.19,47.17 51.37,47.08 51.534,46.916 51.697,46.753 51.861,46.589 52.025,46.425 52.188,46.262 52.352,46.098 52.515,45.935 52.679,45.771 52.843,45.607 53.006,45.444 ; 53.661,44.605 53.816,44.448 53.971,44.291 54.127,44.133 54.282,43.976 54.438,43.819 54.679,43.8 54.92,43.781 55.162,43.762 55.403,43.743 55.645,43.724 55.886,43.705 56.128,43.686 56.369,43.668 56.611,43.649 56.852,43.63 57.093,43.611 57.335,43.592 57.576,43.573 57.818,43.554 58.059,43.535 58.301,43.517 58.9,43.6 58.783,43.479 59.019,43.413 59.255,43.347 59.417,43.185 59.579,43.023 59.741,42.861 59.903,42.699 60.064,42.537 60.226,42.376 60.388,42.214 60.55,42.052 60.712,41.89 60.941,41.89 61.171,41.89 R_USB_DM.1
usb-dm-port: J_USB.7 J_USB.9 U_ESD.3 | length 6.5
  Top w0.25: J_USB.7 33.537,50.65 33.76,50.867 33.773,50.871 v1(33.87,50.905) ; v1(33.65,51.7) 32.856,51.643 J_USB.9 35.066,51.691 35.764,52.348 36.261,52.348 U_ESD.3
  Bottom w0.25: v1(33.65,51.7) 33.654,51.648 33.755,51.648 33.839,51.564 v1(33.87,50.905)
usb-dp-mcu: R_USB_DP.2 U_MAIN.31 | length 14.9
  Top w0.25: U_MAIN.31 60.65,56.156 v1(60.986,55.82) ; v1(61.36,49.589) 61.811,49.138 61.819,49.083 61.835,43.699 R_USB_DP.2
  Bottom w0.25: v1(60.986,55.82) 61.028,55.778 61.028,55.713 61.143,55.598 61.166,55.512 61.167,54.634 61.254,53.316 61.173,49.806 v1(61.36,49.589)
usb-dp-phy: R_USB_DP.1 U_ESD.6 | length 28.4
  Top w0.25: U_ESD.6 40.307,50.45 v1@41.707,49.049 ; v1@41.708,49.049 v1(41.785,48.972) ; v1(60.858,41.367) 62.039,41.329 R_USB_DP.1
  Bottom w0.25: v1(41.785,48.972) 48.56,42.197 53.737,42.206 54.198,41.682 54.255,41.455 54.601,41.122 60.336,41.106 60.378,41.106 60.701,41.428 60.721,41.428 v1(60.858,41.367)
usb-dp-port: J_USB.8 J_USB.10 U_ESD.1 | length 6.1
  Top w0.188: 32.003,51.857 31.998,51.645 32,51.4 32.128,51.297
  Top w0.2: 32,51.95 32.003,51.857 ; 32.128,51.297 32.319,51.297 32.51,51.297 32.702,51.297 J_USB.8
  Top w0.238: 32,51.95 32.148,52.05
  Top w0.25: 32.148,52.05 32.297,52.15 32.481,52.15 32.665,52.15 J_USB.10 ; J_USB.8 33.56,51.179 33.781,51.302 34.273,51.311 34.381,51.313 v1(34.429,51.272) ; v1(35.065,50.808) U_ESD.1
  Bottom w0.25: v1(34.429,51.272) 34.517,51.285 35.03,50.773 v1(35.065,50.808)
USB_CC1: J_USB.6 R_CC1.1 | length 12.6
  Top w0.15: J_USB.6 32.935,50.064 33.511,50.064 33.791,49.784 v1(33.791,49.685) ; v1(33.923,43.312) 33.954,45.33 33.911,47.926 34.35,48.365 34.35,48.377 v1(34.445,48.472) ; v1(33.96,42.088) 34.012,42.036 34.89,41.158 R_CC1.1
  Bottom w0.15: v1(33.791,49.685) 33.767,49.661 33.767,49.61 33.73,49.572 33.55,49.15 34.387,48.472 v1(34.445,48.472) ; v1(33.923,43.312) 33.916,43.295 33.916,43.069 33.96,43.024 v1(33.96,42.088)
USB_CC2: J_USB.12 R_CC2.1 | length 17.3
  Top w0.15: J_USB.12 32.899,53.2 v1(33.8,53.2) ; v1(38.657,40.105) 38.688,40.074 38.688,40.066 38.89,39.864 R_CC2.1
  Bottom w0.15: v1(33.8,53.2) 33.75,53.15 33.246,52.646 33.246,52.612 33.246,45.516 v1(38.657,40.105)
VBUS5: C_LDO_IN.1 C_VBUS.1 J_USB.3 J_USB.4 J_USB.13 J_USB.14 U_ESD.5 U_LDO.1 U_LDO.3 | length 61.3
  Top w0.15: 38.058,59.675 38.45,59.675 38.843,59.675 38.894,59.727
  Top w0.188: U_LDO.1@37.558,60.268 37.666,59.998 38,59.7 38.058,59.675
  Top w0.225: 38.894,59.727 U_LDO.3@39.122,59.955
  Top w0.3: 32.181,53.666 32.554,53.65 J_USB.14 32.849,53.8 ; J_USB.4@32.199,49.15 32.51,49.15 J_USB.4 ; J_USB.3@32.849,49 J_USB.4 ; J_USB.13 32.943,53.95 33.037,53.95 33.13,53.95 33.224,53.95 33.318,53.95 33.412,53.95 33.499,53.95 ; J_USB.4@33.229,49.15 J_USB.4
  Top w0.312: 35.881,54.477 35.918,54.477 v1(36.015,54.574)
  Top w0.375: 31.806,49.431 32.171,49.15 J_USB.4@32.199,49.15 ; 57.702,42.99 58.186,42.992 58.619,43.056
  Top w0.4: 33.989,49.15 34.067,49.227 34.118,49.227 v1(34.126,49.235)
  Top w0.425: 57.218,42.987 57.702,42.99
  Top w0.437: 31.682,53.253 31.838,53.588 32.056,53.588 32.181,53.666
  Top w0.45: 31.527,52.918 31.682,53.253 ; 58.619,43.056 58.815,42.852
  Top w0.475: J_USB.4@33.229,49.15 33.609,49.15 33.989,49.15 ; 33.499,53.95 33.505,53.95 33.599,53.95 ; 58.815,42.852 59.012,42.647
  Top w0.5: 31.527,52.918 31.527,50.036 31.713,49.85 31.806,49.431 ; J_USB.3 J_USB.4@32.849,49 ; J_USB.13@32.849,53.8 J_USB.13 ; C_LDO_IN.1 34.636,61.339 v1(34.636,61.28) ; 33.599,53.95 34.038,53.95 34.476,53.95 34.915,53.95 35.354,53.95 35.617,54.214 35.881,54.477 ; v1(35.102,49.144) 36.544,49.144 37.4,50 37.4,50.8 37.8,51.2 U_ESD.5 46.37,51.4 47.774,49.996 47.774,49.776 54.15,43.4 54.428,43.316 54.775,42.962 54.797,42.976 55.281,42.978 55.765,42.981 56.249,42.983 56.733,42.985 57.218,42.987 ; v1(36.014,60.759) 36.034,60.739 36.236,60.537 U_LDO.1 ; v1(36.383,59.422) 36.383,59.471 U_LDO.1 ; U_LDO.1@37.558,60.268 37.558,60.43 U_LDO.1 ; U_LDO.3@39.122,59.955 39.35,60.183 U_LDO.3 ; 59.012,42.647 59.354,42.299 59.695,41.952 60.9,40.4 62.312,40.4 C_VBUS.1
  Bottom w0.5: v1(34.126,49.235) 35.011,49.235 v1(35.102,49.144) ; v1(34.636,61.28) 35.156,60.759 v1(36.014,60.759) ; v1(36.015,54.574) 36.015,55.062 36.015,55.55 36.015,56.038 36.015,56.526 36.015,57.015 36.015,57.503 36.015,57.991 36.015,58.479 36.015,58.967 36.311,59.263 36.311,59.35 v1(36.383,59.422)
VCC_3V3: C_3V3_BULK.1 C_EPD_BOOST_IN.1 C_EPD_VDD.1 C_EPD_VDD_HF.1 C_LDO_OUT.1 C_MCU_BULK.1 C_MCU_VDD.1 C_VUSB.1 J_DEBUG.1 J_DISPLAY.15 J_DISPLAY.16 L_EPD_BOOST.1 R_DISPLAY_CS.2 R_DISPLAY_RESET.2 R_MCU_RESET.2 U_LDO.5 U_MAIN.29 U_MAIN.40 | length 144.5
  Top w0.125: 100.176,53.77 100.301,53.773 100.525,53.489 100.743,53.268
  Top w0.138: 99.957,53.697 100.029,53.77 100.176,53.77
  Top w0.169: 100.743,53.268 J_DISPLAY.16@100.948,53.083
  Top w0.262: 99.785,53.525 99.957,53.697 ; J_DISPLAY.16@100.948,53.083 101.153,52.897
  Top w0.3: 59.65,56.125 59.65,57.785 59.65,57.418 U_MAIN.29 59.667,57.033 59.667,56.65 U_MAIN.29@59.667,56.3 ; 62.3,51.65 62.375,51.65 62.488,51.65 62.6,51.65 62.713,51.65 62.825,51.65 62.937,51.65 U_MAIN.40 ; U_MAIN.40@62.628,51.65 U_MAIN.40 ; U_MAIN.40@63.8,51.65 63.725,51.65 63.612,51.65 63.5,51.65 63.388,51.65 63.275,51.65 63.163,51.65 U_MAIN.40 ; 101.25,52.8 J_DISPLAY.15 101.4,52.8 ; J_DISPLAY.16@101.4,53 J_DISPLAY.16
  Top w0.312: 62.205,51.65 U_MAIN.40@62.628,51.65
  Top w0.337: 61.915,51.636 62.3,51.65 ; 75.597,36.888 75.798,37.043 76,37.199
  Top w0.35: 82.574,39.797 82.574,39.974 v1(82.6,40) ; 99.613,53.353 99.785,53.525
  Top w0.363: 61.783,51.65 62.205,51.65 ; 75.4,36.666 75.597,36.888 ; 76,37.199 76.3,37.465
  Top w0.375: 61.529,51.623 61.915,51.636
  Top w0.394: v1(99.643,48.871) 99.631,49.49 C_EPD_VDD_HF.1
  Top w0.4: 61.144,51.609 61.529,51.623 ; 82.325,39.548 82.574,39.797 ; 101.153,52.897 101.25,52.8
  Top w0.425: 61.492,51.941 61.783,51.65
  Top w0.437: 63.8,51.65 63.837,51.65
  Top w0.45: U_LDO.5 37.736,58.549 38.022,58.835 38.309,59.121 39.475,59.407 39.822,59.5 40.006,59.769 40.191,60.038 40.375,60.307 40.675,60.607 40.975,60.907 41.275,61.207 41.575,61.507 41.575,61.953 C_LDO_OUT.1 41.856,62.2 42.138,62 42.419,61.8 42.663,61.525 43.787,61.525 44.013,61.75 43.974,62.021 44.048,62.443 44.122,62.864 44.196,63.286 44.27,63.707 44.574,63.38 44.879,63.053 45.183,62.727 C_3V3_BULK.1 ; J_DEBUG.1 45.488,67.918 C_3V3_BULK.1 ; v1(53.586,41.787) 53.759,41.959 53.773,41.959 53.91,42.097 R_MCU_RESET.2 54.6,41.713 v1(54.693,41.705) ; v1(58.026,40.199) 58.026,39.849 58.213,39.662 C_VUSB.1 ; v1(58.218,50.582) 58.236,50.6 58.586,50.793 58.936,50.987 59.287,51.181 59.637,51.375 59.988,51.569 60.373,51.582 60.758,51.596 61.144,51.609 ; v1(59.411,53.402) 59.472,53.341 59.627,53.341 59.67,53.384 59.982,53.384 60.295,53.384 v1(60.607,53.384) ; 59.65,56.125 59.425,55.9 53.35,55.9 52.166,58.003 51.849,57.686 51.532,57.369 51.215,57.052 50.898,56.735 50.581,56.418 50.264,56.101 49.947,55.784 49.63,55.467 C_MCU_BULK.1 49.034,55.428 48.756,55.707 48.478,55.985 48.4,57.925 48.4,58.6 48.199,59.26 48.199,59.689 47.898,59.99 47.597,60.291 46.709,60.683 46.693,61.195 46.391,61.496 46.09,61.797 45.789,62.099 C_3V3_BULK.1 ; v1(59.667,55.885) 59.667,56.268 59.667,56.3 ; v1(60.78,52.587) 60.883,52.522 60.911,52.522 61.202,52.231 61.492,51.941 ; 63.837,51.65 63.95,51.65 C_MCU_VDD.1 66.4,52.3 67.6,52.3 67.6,51.1 66.711,50.16 66.991,49.885 67.27,49.61 67.55,49.335 67.549,49.043 67.549,48.751 67.861,48.439 68.173,48.128 68.485,47.816 68.797,47.504 69.109,47.193 69.421,46.881 69.733,46.569 70.045,46.257 70.357,45.946 70.669,45.634 70.981,45.322 71.293,45.011 71.605,44.699 71.917,44.387 72.229,44.076 72.541,43.764 72.853,43.452 73.165,43.14 73.477,42.829 73.79,42.517 74.102,42.205 74.414,41.894 74.726,41.582 75.175,40.825 75.662,40.647 75.974,40.335 76.525,39.925 76.598,39.712 R_DISPLAY_CS.2 ; C_EPD_BOOST_IN.1 75.098,35.56 75.258,35.72 75.246,36.039 75.234,36.358 75.1,36.4 75.4,36.666 ; 76.3,37.465 76.6,37.731 76.9,37.997 76.902,38.348 76.905,38.699 76.907,39.049 R_DISPLAY_CS.2 ; 82.325,39.548 82.325,39.165 82.325,38.783 L_EPD_BOOST.1 81.325,39.4 R_DISPLAY_RESET.2 79.45,38.8 78.55,38.575 78.244,39 78.044,39.2 77.844,39.4 77.533,39.4 77.221,39.4 R_DISPLAY_CS.2 ; 99.613,53.353 99.613,53.036 99.613,52.718 C_EPD_VDD.1 99.725,52.288 C_EPD_VDD_HF.1 ; 101.4,52.8 101.4,53
  Bottom w0.325: v1(53.586,41.787) 53.556,41.602 53.846,41.319
  Bottom w0.4: 53.846,41.319 53.997,40.966 54.357,40.717 ; v1(60.607,53.384) 60.666,53.325 v1@60.666,53.273
  Bottom w0.437: v1(60.78,52.587) 60.783,52.854
  Bottom w0.45: 54.357,40.717 54.717,40.468 55.007,40.184 55.297,39.901 55.587,39.617 55.877,39.334 56.167,39.05 56.458,38.767 56.573,38.778 56.845,39.05 57.117,39.322 57.39,39.595 57.662,39.867 57.934,40.139 57.966,40.139 v1(58.026,40.199) ; v1(54.693,41.705) 54.704,41.704 54.704,41.716 58.218,45.229 v1(58.218,50.582) ; v1(59.411,53.402) 59.411,53.834 59.411,54.267 59.411,54.699 59.411,55.131 59.411,55.564 59.648,55.801 59.648,55.866 v1(59.667,55.885) ; v1@60.666,53.273 60.786,53.122 60.783,52.854 ; v1(82.6,40) 83.028,40 83.456,40 83.884,40 84.312,40 84.74,40 85.168,40 85.595,40 86.023,40 86.451,40 87.577,40.27 87.847,40.54 88.117,40.81 88.387,41.08 88.657,41.35 88.928,41.62 89.229,41.922 89.531,42.224 89.833,42.526 90.135,42.828 90.437,43.13 90.739,43.432 91.041,43.734 91.343,44.036 91.645,44.338 91.947,44.64 92.249,44.941 92.551,45.243 92.853,45.545 93.154,45.847 96.106,46.149 96.548,46.149 96.813,46.149 97.106,46.443 97.399,46.736 97.693,47.029 97.986,47.323 98.279,47.616 98.573,47.909 98.866,48.203 99.16,48.496 99.453,48.789 99.601,48.789 v1(99.643,48.871)
pads on no net: J_DISPLAY.1 J_DISPLAY.4 J_DISPLAY.6 J_DISPLAY.7 J_DISPLAY.19 J_DISPLAY.25 J_DISPLAY.26 J_USB.5 J_USB.11 J_USB.NPTH-1 J_USB.NPTH-2 U_LDO.4 U_MAIN.1 U_MAIN.2 U_MAIN.3 U_MAIN.4 U_MAIN.5 U_MAIN.6 U_MAIN.7 U_MAIN.8 U_MAIN.9 U_MAIN.10 U_MAIN.11 U_MAIN.14 U_MAIN.15 U_MAIN.16 U_MAIN.17 U_MAIN.18 U_MAIN.19 U_MAIN.20 U_MAIN.21 U_MAIN.22 U_MAIN.23 U_MAIN.24 U_MAIN.25 U_MAIN.26 U_MAIN.27 U_MAIN.28 U_MAIN.33 U_MAIN.34 U_MAIN.35 U_MAIN.36 U_MAIN.37 U_MAIN.39 U_MAIN.43 U_MAIN.44 U_MAIN.45 U_MAIN.46 U_MAIN.47 U_MAIN.48 U_MAIN.49 U_MAIN.50 U_MAIN.54 U_MAIN.55 U_MAIN.56 U_MAIN.57 U_MAIN.62 U_MAIN.63 U_MAIN.64

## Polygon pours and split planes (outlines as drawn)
GND on Bottom (solid): 107.1,77.1 25.7,77.1 25.7,25.7 107.1,25.7
GND on Bottom (solid): 33.521,51.323 33.521,51.097 33.534,51.122 33.525,51.322
GND on Bottom (solid): 60.589,55.785 60.164,55.36 60.164,55.079 60.237,55.086 60.315,55.078 60.39,55.056 60.459,55.019 60.52,54.969 60.57,54.908 60.607,54.839 60.629,54.764 60.637,54.686 60.629,54.608 60.607,54.533 60.57,54.464 60.534,54.42 60.534,54.348 60.534,54.102 60.534,53.855 60.528,53.792 60.523,53.774 60.529,53.776 60.607,53.784 60.685,53.776 60.76,53.754 60.827,53.718 60.829,53.717 60.903,53.678 60.904,53.677 60.842,54.613 60.844,54.613 60.842,54.634 60.841,55.441 60.829,55.453 60.764,55.487 60.703,55.537 60.653,55.598 60.616,55.667 60.594,55.742
GND on Bottom (solid): 96.863,53.399 96.645,53.399 98.588,51.457 102.027,51.457 102.016,51.494 101.577,51.933 101.544,51.973 101.52,52.018 101.506,52.066 101.501,52.117 101.501,52.294 100.56,53.235 100.523,53.166 100.474,53.105 100.413,53.056 100.344,53.019 100.269,52.996 100.191,52.988 100.113,52.996 100.038,53.019 99.969,53.056 99.908,53.105 99.864,53.159 97.211,53.159 97.16,53.164 97.111,53.179 97.066,53.203 97.027,53.235
GND on Bottom (solid): 58.986,54.884 58.923,54.85 58.848,54.828 58.77,54.82 58.692,54.828 58.648,54.841 58.648,52.759 58.643,52.709 58.628,52.66 58.604,52.615 58.572,52.576 57.316,51.32 57.316,51.138 59.257,53.007 59.248,53.009 59.175,53.049 59.11,53.101 59.058,53.166 59.018,53.239 58.994,53.319 58.986,53.402 58.986,53.834 58.986,54.267 58.986,54.699
GND on Bottom (solid): 102.152,50.289 102.123,50.286 100.09,50.286 100.782,49.593 102.309,49.593 102.275,49.656 102.253,49.731 102.245,49.809 102.253,49.887 102.275,49.962 102.312,50.031 102.362,50.092 102.423,50.142 102.492,50.179 102.52,50.187 102.52,50.22 102.478,50.208 102.4,50.2 102.322,50.208 102.247,50.23 102.178,50.267
GND on Bottom (solid): 99.153,49.09 98.075,48.988 95.613,46.526 96.063,46.572 96.063,46.57 96.106,46.574 96.548,46.574 96.637,46.574 96.806,46.743 97.099,47.036 97.392,47.33 97.686,47.623 97.979,47.916 98.272,48.21 98.566,48.503 98.859,48.797 99.152,49.09
GND on Bottom (solid): 59.686,48.003 59.686,47.207 59.699,47.218

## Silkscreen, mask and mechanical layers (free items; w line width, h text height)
Top Overlay:
  text "2L • BOTTOM GND POUR" at 48.4,75.4 h0.48
  text "ER-CON24HT-1 • 4-WIRE SPI" at 84.4,75.4 h0.55
  text "ER-EPD0213-2B" at 81.4,28.9 h0.58
  text "QUICK CONFIGURE • SCREEN" at 66.4,27.4 h0.72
